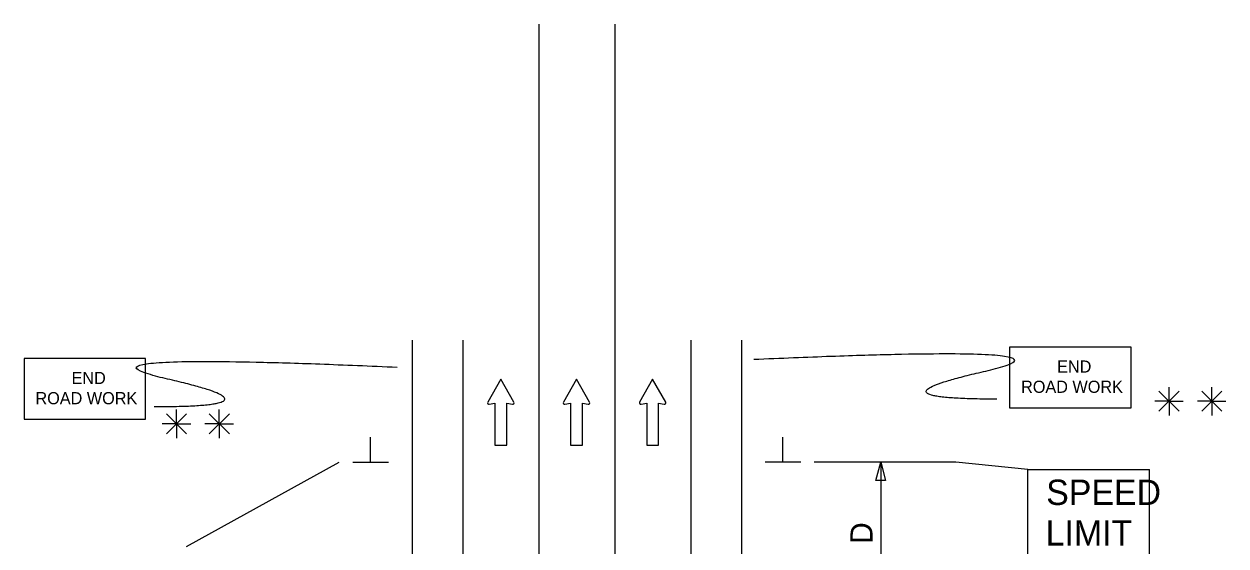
# Model space of a CAD drawing. Extents: x 16553 to 18478, y 5759 to 7026.
# Drawn here: x 16749.1 to 17128.7, y 6861.7 to 7026.4 of the extents above; entities that cross this region are included whole.
import ezdxf

# ---------------------------------------------------------------- set-up
doc = ezdxf.new("R2010")
doc.units = 0
for name, color, linetype in [('ALI_LEGAL_EX', 7, 'Continuous'), ('MT_SCRATCH_LEVEL_E', 7, 'Continuous'), ('PAVT_EDGE_EX', 7, 'Continuous'), ('TRAFFIC_SIGNS_PR', 7, 'Continuous'), ('TYPICAL_TEXT_DIMEN_PR', 7, 'Continuous')]:
    doc.layers.add(name, color=color, linetype=linetype)

msp = doc.modelspace()

# ---------------------------------------------------------------- linework, layer by layer
at = {"layer": 'ALI_LEGAL_EX'}
for p, q in [((16911.66, 7026.35), (16911.66, 6197.16)), ((16935.66, 7026.35), (16935.66, 6197.16)), ((16935.66, 7026.35), (16935.66, 6197.16))]:
    msp.add_line(p, q, dxfattribs=at)
for points in [[(16911.66, 6926.35), (16911.66, 6901.35)], [(16935.66, 6926.35), (16935.66, 6901.35)]]:
    msp.add_lwpolyline(points, dxfattribs=at)
at = {"layer": 'MT_SCRATCH_LEVEL_E'}
for p, q in [((16899.66, 6914.3), (16895.55, 6907.06)), ((16903.81, 6907.06), (16899.66, 6914.3)), ((16923.57, 6914.3), (16919.46, 6907.06)), ((16927.71, 6907.06), (16923.57, 6914.3)), ((16947.62, 6914.3), (16943.51, 6907.06)), ((16951.77, 6907.06), (16947.62, 6914.3)), ((16896.03, 6906.37), (16897.81, 6906.69)), ((16897.81, 6906.69), (16897.81, 6893.43)), ((16901.55, 6893.43), (16901.55, 6906.69)), ((16901.55, 6906.69), (16903.33, 6906.37)), ((16919.94, 6906.37), (16921.72, 6906.69)), ((16921.72, 6906.69), (16921.72, 6893.43)), ((16925.46, 6893.43), (16925.46, 6906.69)), ((16925.46, 6906.69), (16927.23, 6906.37)), ((16943.99, 6906.37), (16945.77, 6906.69)), ((16945.77, 6906.69), (16945.77, 6893.43)), ((16949.51, 6893.43), (16949.51, 6906.69)), ((16949.51, 6906.69), (16951.29, 6906.37)), ((16897.81, 6893.43), (16901.55, 6893.43)), ((16921.72, 6893.43), (16925.46, 6893.43)), ((16945.77, 6893.43), (16949.51, 6893.43))]:
    msp.add_line(p, q, dxfattribs=at)
for centre, start, end in [((16895.96, 6906.83), 150.4248, 279.9638), ((16903.4, 6906.83), 260.0362, 29.7731), ((16919.86, 6906.83), 150.4248, 279.9638), ((16927.3, 6906.83), 260.0362, 29.7731), ((16943.92, 6906.83), 150.4248, 279.9638), ((16951.36, 6906.83), 260.0362, 29.7731)]:
    msp.add_arc(centre, 0.463, start, end, dxfattribs=at)
at = {"layer": 'PAVT_EDGE_EX'}
for p, q in [((16871.66, 6926.66), (16871.66, 6223.96)), ((16887.66, 6926.66), (16887.66, 6223.96)), ((16959.66, 6926.66), (16959.66, 6223.96)), ((16975.66, 6926.66), (16975.66, 6223.96))]:
    msp.add_line(p, q, dxfattribs=at)
at = {"layer": 'TRAFFIC_SIGNS_PR'}
for p, q in [((17066.18, 6885.75), (17104.58, 6885.75)), ((17066.18, 6837.75), (17066.18, 6885.75)), ((17104.58, 6837.75), (17104.58, 6885.75))]:
    msp.add_line(p, q, dxfattribs=at)
for points in [[(16749.09, 6901.65), (16787.49, 6901.65), (16787.49, 6920.85), (16749.09, 6920.85)], [(17060.4, 6905.24), (17098.8, 6905.24), (17098.8, 6924.44), (17060.4, 6924.44)]]:
    msp.add_lwpolyline(points, close=True, dxfattribs=at)
for points in [[(17056.4, 6908), (17013.89, 6908), (17090.41, 6925.41), (16979.62, 6920.47)], [(16790.14, 6905.64), (16832.65, 6905.64), (16756.13, 6923.05), (16866.92, 6918.11)]]:
    msp.add_open_spline(points, degree=2, dxfattribs=at)
at = {"layer": 'TYPICAL_TEXT_DIMEN_PR'}
for p, q in [((17107.55, 6910.56), (17113.93, 6904.18)), ((17113.93, 6910.56), (17107.55, 6904.18)), ((17110.74, 6907.37), (17110.74, 6911.82)), ((17121.06, 6910.56), (17127.43, 6904.18)), ((17127.43, 6910.56), (17121.06, 6904.18)), ((17124.24, 6907.37), (17124.24, 6911.82)), ((17110.74, 6907.37), (17106.21, 6907.37)), ((17110.74, 6907.37), (17113.93, 6907.37)), ((17110.74, 6907.37), (17115.22, 6907.37)), ((17110.74, 6907.37), (17110.74, 6902.87)), ((17124.24, 6907.37), (17119.71, 6907.37)), ((17124.24, 6907.37), (17127.43, 6907.37)), ((17124.24, 6907.37), (17128.72, 6907.37)), ((17124.24, 6907.37), (17124.24, 6902.87)), ((16794.08, 6903.41), (16800.45, 6897.03)), ((16800.45, 6903.41), (16794.08, 6897.03)), ((16797.26, 6900.22), (16797.26, 6904.68)), ((16807.58, 6903.41), (16813.96, 6897.03)), ((16813.96, 6903.41), (16807.58, 6897.03)), ((16810.77, 6900.22), (16810.77, 6904.68)), ((16797.26, 6900.22), (16792.73, 6900.22)), ((16797.26, 6900.22), (16800.45, 6900.22)), ((16797.26, 6900.22), (16801.74, 6900.22)), ((16797.26, 6900.22), (16797.26, 6895.72)), ((16810.77, 6900.22), (16806.24, 6900.22)), ((16810.77, 6900.22), (16813.96, 6900.22)), ((16810.77, 6900.22), (16815.25, 6900.22)), ((16810.77, 6900.22), (16810.77, 6895.72)), ((16858.54, 6888.16), (16858.54, 6895.95)), ((16988.79, 6888.16), (16988.79, 6895.95)), ((16800.42, 6861.55), (16848.66, 6888.16)), ((16852.91, 6888.16), (16864.16, 6888.16)), ((16994.41, 6888.16), (16983.16, 6888.16)), ((17043.4, 6888.16), (16998.66, 6888.16)), ((17018.09, 6882.3), (17019.66, 6888.16)), ((17019.66, 6888.16), (17019.66, 6838.16)), ((17019.66, 6888.16), (17021.23, 6882.3)), ((17066.18, 6885.75), (17043.4, 6888.16)), ((17019.66, 6882.3), (17018.09, 6882.3)), ((17021.23, 6882.3), (17019.66, 6882.3))]:
    msp.add_line(p, q, dxfattribs=at)

# ---------------------------------------------------------------- texts
at = {"layer": 'TRAFFIC_SIGNS_PR'}
for s, height, p in [('END', 3.831, (17075.4, 6916.37)), ('END', 3.831, (16764.09, 6912.77)), ('ROAD WORK', 3.831, (17064.01, 6909.99)), ('ROAD WORK', 3.831, (16752.7, 6906.39)), ('SPEED', 8, (17071.95, 6874.61)), ('LIMIT', 8, (17071.79, 6861.81))]:
    msp.add_text(s, height=height, dxfattribs=at).set_placement(p)
at = {"layer": 'TYPICAL_TEXT_DIMEN_PR'}
msp.add_text('D', height=7, rotation=90, dxfattribs=at).set_placement((17017.1, 6862.38))

doc.saveas('drawing.dxf')
